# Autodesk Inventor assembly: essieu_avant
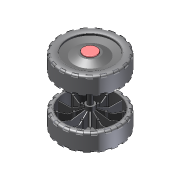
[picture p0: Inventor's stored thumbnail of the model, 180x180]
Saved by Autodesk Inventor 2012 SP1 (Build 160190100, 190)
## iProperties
Created: 2011-01
Part Number: essieu_avant
Document SubType Name: Assembly
Designer: eric
Mass: 610.809 g
Surface Area: 3296.9 cm^2
Volume: 610.809 cm^3
Density: 1 g/cm^3
Author: eric
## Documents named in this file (2)
- D:\Cours\Inventor salle SI\chariot_de_golf_2008\chariot_de_golf_trolem\essieu_avant.iam
- D:\Cours\Inventor salle SI\chariot_de_golf_2008\chariot_de_golf_trolem\5.1roues_montees_axe_Defaut.iam
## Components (1 placed, 1 different names)
1. essieu:1 [sub-assembly]
